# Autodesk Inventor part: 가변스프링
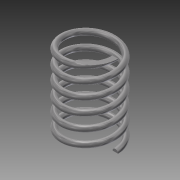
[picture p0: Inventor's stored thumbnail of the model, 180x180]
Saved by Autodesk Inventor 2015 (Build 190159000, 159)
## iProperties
Created: 2015-10
Part Number: 가변스프링
Material: Steel, Mild
Document SubType Name: Modeling
Designer: youjin05
Mass: 114.557 g
Surface Area: 118.327 cm^2
Volume: 14.5932 cm^3
Density: 7.85 g/cm^3
Appearance: Semi-Polished
Author: youjin05
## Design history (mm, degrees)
sketch "Sketch1"
  geometry: L1 (0, 0)-(-22.5, 0); L2 (-22.5, 0)-(-22.5, 73.25); L3 (-22.5, 73.25)-(0, 73.25); L4 (0, 73.25)-(0, 0); C1 r 2.5 at (-22.5, 0)
  constraints: 8 end point, 2 parallel, 1 centre point, 1 coincident, 1 horizontal, 1 perpendicular
  dimensions: "d0" = 73.25 distance between parallel lines of L1 L3 (derived); "d1" = 45 diameter of L2 L4; "d2" = 5 diameter of C1
coil "Coil1" pitch "d3" = 10; turns "d5" = 6; dims "d4" = 73.25 (= d0), "d6" = 0, angle "d7" = 90 deg, angle "d8" = 90 deg, "d9" = 0, "d10" = 0
sketch "Sketch2"
  geometry: L1 (25, 0)-(20, 0) reference; 1 further point
  constraints: 1 horizontal alignment
extrude "Extrusion1" cut sketch "Sketch2" stored distance "d11" = 10; taper "d12" = 0 deg
workplane "Work Plane1"
sketch "Sketch3"
  geometry: L1 (20, 0)-(25, 0) reference; 1 further point
  constraints: 1 horizontal alignment
extrude "Extrusion2" cut sketch "Sketch3" stored distance "d13" = 10; taper "d14" = 0 deg
body "Solid1"
node "Project Cut Edges1"
node "Project Cut Edges2"
